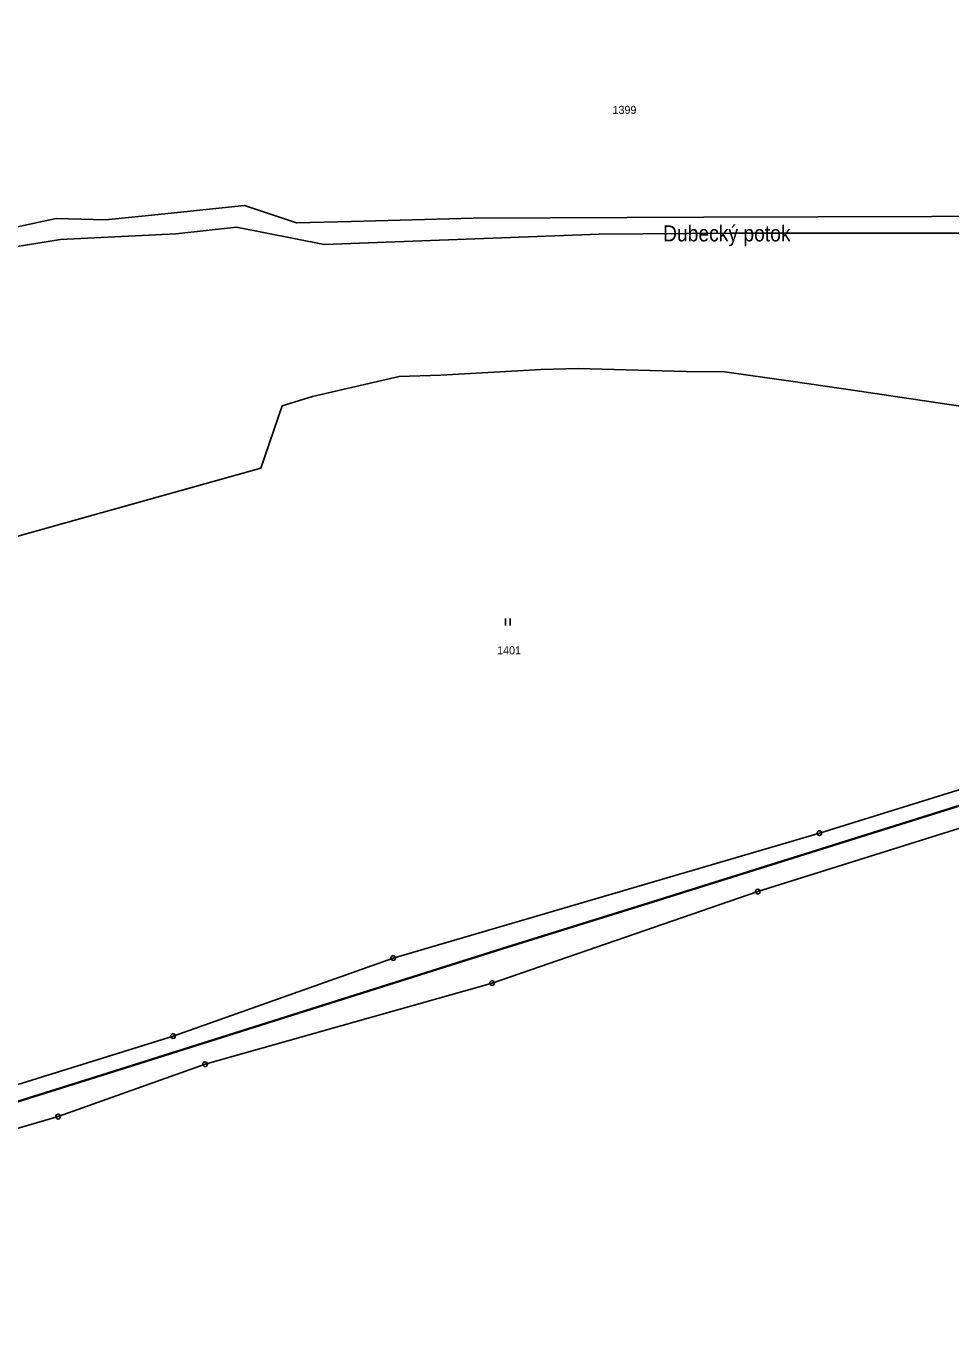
# Model space of a CAD drawing. Extents: x -872229 to -869198, y -1075981 to -1074329.
# Drawn here: x -870236.3 to -870040, y -1075493.1 to -1075213.8 of the extents above; entities that cross this region are included whole.
import ezdxf
from ezdxf.enums import TextEntityAlignment as Align

# ---------------------------------------------------------------- set-up
doc = ezdxf.new("R2010")
doc.units = 0
doc.header["$LTSCALE"] = 0.68
for name, color, linetype, lineweight in [('1', 7, 'Continuous', 25), ('3', 7, 'Continuous', 25), ('6', 7, 'Continuous', 25), ('7', 7, 'Continuous', 13), ('8', 7, 'Continuous', 25)]:
    doc.layers.add(name, color=color, linetype=linetype, lineweight=lineweight)
doc.layers.add('2', color=7, linetype='Continuous')

msp = doc.modelspace()

# ---------------------------------------------------------------- linework, layer by layer
at = {"layer": '1'}
for points in [[(-870385.12, -1075316.07), (-870355.23, -1075301.89), (-870314.21, -1075282.93), (-870280.58, -1075266.36), (-870265.86, -1075261.9), (-870249.15, -1075258.69), (-870230, -1075254.57), (-870219.5, -1075254.87), (-870207.6, -1075253.65), (-870190, -1075251.81), (-870178.96, -1075255.5), (-870167.23, -1075255.17), (-870141.46, -1075254.46), (-870092.41, -1075254.3), (-870019.81, -1075254.06), (-869952.16, -1075254.08), (-869902.23, -1075254.21), (-869809.43, -1075253.56), (-869784.98, -1075249.67), (-869765.49, -1075244.15), (-869696.7, -1075225.43), (-869659.27, -1075213.75)], [(-870389.39, -1075322.98), (-870381.24, -1075318.31), (-870366.64, -1075311.61), (-870346.71, -1075301.64), (-870331.27, -1075294.54), (-870292.97, -1075277.13), (-870277.78, -1075269.99), (-870255.58, -1075264.06), (-870240.85, -1075260.92), (-870229.06, -1075259.04), (-870204.53, -1075257.8), (-870191.67, -1075256.42), (-870173.08, -1075260.11), (-870114.64, -1075257.88), (-870086.74, -1075257.68), (-870033.35, -1075257.7)], [(-870249.5, -1075325.23), (-870223.98, -1075318.04), (-870186.49, -1075307.57), (-870182, -1075294.31), (-870175.53, -1075292.39), (-870157.15, -1075288.1), (-870148.32, -1075287.84), (-870126.97, -1075286.65), (-870119.12, -1075286.39), (-870096.19, -1075287.05), (-870088.07, -1075287.11), (-870073.97, -1075289.09), (-870059.41, -1075291.2), (-870040.81, -1075293.97), (-870019.39, -1075297.01)], [(-869861.67, -1075370.56), (-869878.14, -1075367.33), (-869908.77, -1075363.47), (-869918.42, -1075363.79), (-869963.81, -1075365.31), (-869991.44, -1075371.29), (-870013.06, -1075376.14), (-870080.98, -1075397.47), (-870137.41, -1075416.91), (-870198.36, -1075434.14), (-870229.56, -1075445.28), (-870312.6, -1075469.56), (-870365.19, -1075486.42), (-870398.17, -1075493.93), (-870445.72, -1075497.57), (-870473.49, -1075498.03), (-870483.95, -1075496.85)], [(-870486.5, -1075484.99), (-870484.52, -1075485.24), (-870480.75, -1075482.95), (-870462.19, -1075488.41), (-870441.81, -1075489.8), (-870382.34, -1075482.14), (-870362.98, -1075477.23), (-870347.8, -1075472.63), (-870325.84, -1075466.04), (-870298.48, -1075457.59), (-870279.74, -1075451.72), (-870275.31, -1075449.42), (-870268.89, -1075443.67), (-870252.29, -1075442.86), (-870205.14, -1075428.17), (-870158.39, -1075411.62), (-870067.91, -1075385.07), (-870005.01, -1075365.55)]]:
    msp.add_lwpolyline(points, dxfattribs=at)
at = {"layer": '3'}
for p, q in [((-870134.551, -1075341.02), (-870134.551, -1075339.52)), ((-870133.55, -1075341.02), (-870133.55, -1075339.52))]:
    msp.add_line(p, q, dxfattribs=at)
at = {"layer": '6', "lineweight": 35}
msp.add_line((-870135.1, -1075409.54), (-870103.28, -1075399.64), dxfattribs=at)
for points in [[(-870103.28, -1075399.64), (-870067.42, -1075388.4), (-870019.78, -1075373.46)], [(-870252.84, -1075446.64), (-870219.18, -1075436.13), (-870135.1, -1075409.54)]]:
    msp.add_lwpolyline(points, dxfattribs=at)
at = {"layer": '8'}
for centre, radius in [((-870067.91, -1075385.0699), 0.5), ((-870067.91, -1075385.0699), 0.0303), ((-870080.98, -1075397.4699), 0.5), ((-870080.98, -1075397.4699), 0.0303), ((-870158.39, -1075411.6199), 0.5), ((-870158.39, -1075411.6199), 0.0303), ((-870137.41, -1075416.9099), 0.5), ((-870137.41, -1075416.9099), 0.0303), ((-870205.14, -1075428.1699), 0.5), ((-870205.14, -1075428.1699), 0.0303), ((-870198.36, -1075434.1399), 0.5), ((-870198.36, -1075434.1399), 0.0303), ((-870229.56, -1075445.2799), 0.5), ((-870229.56, -1075445.2799), 0.0303)]:
    msp.add_circle(centre, radius, dxfattribs=at)

# ---------------------------------------------------------------- texts
at = {"layer": '2'}
for s, p in [('1399', (-870111.82, -1075232.35)), ('1401', (-870136.33, -1075347.11))]:
    msp.add_text(s, height=1.7, dxfattribs=at).set_placement(p)
at = {"layer": '7', "width": 0.9}
msp.add_text('Dubecký potok', height=3.4, dxfattribs=at).set_placement((-870087.57, -1075259.42), align=Align.CENTER)

doc.saveas('drawing.dxf')
